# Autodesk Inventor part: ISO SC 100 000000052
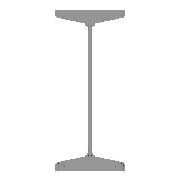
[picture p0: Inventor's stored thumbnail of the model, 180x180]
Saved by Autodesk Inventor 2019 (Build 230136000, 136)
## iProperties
_CCFamilyMember: 1
_CCFamilyDisplayName: ISO 657/16 - 1980 - Poutres en acier laminées à chaud - Partie 16: profilés en H (série métrique) - Cotes et propriétés de section
_FrameMemberDoc: Frame Member File
_Version: 15.0.0
_GetPNFromCC: 1
Created: 2018-07
Part Number: ISO SC 100 000000052
Material: Acier, doux
Description: Poutres en acier laminées à chaud - Partie 16: profilés en H (série métrique) - Cotes et propriétés de section
Document SubType Name: Modeling
Standard: ISO
Designer: Fabian Perrée
Standard Revision: First edition 1980-02-15
Standards Organization: ISO
Language: fr-FR
Size Designation: SC 100
Categories: <MemberInstance><Categories><Category DisplayName="Profilés" InternalName="089c4875-fa83-4c05-b084-43b9cc11f5ed" Mnemonic="GRDR"><CategoryParameter DisplayName=
Stock Number: SC 100
Density: 7.85 g/cm^3
Appearance: Semi-poli
Mass: 62799.5 g
Surface Area: 17060.8 cm^2
Volume: 7999.94 cm^3
IsCustomPart: 1
G_W: 100,000 mm
G_H: 100,000 mm
+B7F31D84-8E7F-44BF-867D-18DAA1A1DD99+DETAILDECOUPE1: Angle de coupe 67,38 deg
G_L: 3183,333 mm
+959F2517-F8C4-4F8C-BEA7-D48C5E0A7FF3+DETAILDECOUPE2: Angle de coupe 67,38 deg
Author: Fabian Perrée
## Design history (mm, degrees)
node "Plan de départ"
node "Plan de fin"
sketch "Esquisse"
  geometry: L1 (-3, 0)-(-3, -26.266); L2 (-13.33, -38.149)-(-44.835, -42.577); L3 (-50, -48.518)-(-50, -50); L4 (-50, -50)-(0, -50); L5 (-26.5, -50)-(-26.5, -40); L6 (-61.333, 0)-(81.777, 0); L7 (0, 0)-(0, -50); L8 (0, -60)-(0, 80); L9 (3, 0)-(3, -26.266); L10 (13.33, -38.149)-(44.835, -42.577); L11 (50, -48.518)-(50, -50); L12 (50, -50)-(0, -50); L13 (-3, 0)-(0, 0); L14 (-3, 0)-(-3, 26.266); L15 (-13.33, 38.149)-(-44.835, 42.577); L16 (-50, 48.518)-(-50, 50); L17 (-50, 50)-(0, 50); L18 (50, 48.518)-(50, 50); L19 (13.33, 38.149)-(44.835, 42.577); L20 (3, 0)-(3, 26.266); L21 (50, 50)-(0, 50); L22 (0, 108)-(0, -88) reference; L23 (-89.955, 0)-(110.399, 0) reference; A1 r 6 centre (-44, 48.518) between (-50, 48.518) and (-44.835, 42.577); A2 r 6 centre (44, 48.518) between (44.835, 42.577) and (50, 48.518); A3 r 6 centre (44, -48.518) between (50, -48.518) and (44.835, -42.577); A4 r 6 centre (-44, -48.518) between (-44.835, -42.577) and (-50, -48.518); A5 r 12 centre (-15, 26.266) between (-3, 26.266) and (-13.33, 38.149); A6 r 12 centre (15, 26.266) between (13.33, 38.149) and (3, 26.266); A7 r 12 centre (15, -26.266) between (3, -26.266) and (13.33, -38.149); A8 r 12 centre (-15, -26.266) between (-13.33, -38.149) and (-3, -26.266); 14 further points
  constraints: 42 end point, 24 point on line, 17 symmetric about line, 16 point on circle, 16 tangent, 8 centre point, 6 equal radius, 4 collinear, 2 perpendicular, 12 other
  dimensions: "d1" = 10 vertical distance of L3.end L5.end (= G_T1); "d2" = 23.5 distance between parallel lines of L5 L3 (= -0.25 x G_T + 0.25 x G_W); "d3" = 3 distance between parallel lines of L1 L7 (= 0.5 x G_T); "d4" = 50 distance between parallel lines of L7 L3 (= 0.5 x G_W); "d9" = 50 distance from line of L1.start L4 (= 0.5 x G_H); "d14" = 98 deg angle of L2 L1 (= G_NG); "d15" = 6 radius of A1 (= G_ER); "d16" = 12 radius of A5 (= G_IR)
extrude "Corps" new body sketch "Esquisse" stored distance "d5" = 3183.33333 (= G_L); taper "d6" = 0 deg
node "Driven Length"
  sketch "Sketch3"
    geometry: L1 (0, 0)-(10, 0) reference
    constraints: 2 end point, 1 horizontal
  workplane "Work Plane3"
  sketch "Sketch4"
    geometry: L1 (-2, 66.667)-(12, 66.667) reference; L2 (-2, 3250)-(12, 3250) reference
    dimensions: "d20" = 3183.33333 distance between parallel lines of L1 L2 (derived)
node "Plan de construction4"
feature "Scission1"
node "Plan de construction5"
feature "Scission2"
body "Solid1"
other parameters: "G_W" = 100 (= G_H) [user parameter; used in 2 equation terms], "G_H" = 100 [user parameter; used in 2 equation terms], "G_T" = 6 [user parameter; used in 2 equation terms], "G_T1" = 10 [user parameter; used in 1 equation term], "G_L" = 3183.33333 (= d20) [user parameter; used in 1 equation term], "G_ER" = 6 [user parameter; used in 1 equation term], "G_IR" = 12 [user parameter; used in 1 equation term], "G_NG" = 98 deg [user parameter; used in 1 equation term], "G_OFFSET_START" = -66.66667 [user parameter; used in 1 equation term], "G_OFFSET_END" = 0 [user parameter; used in 1 equation term], "d17" = 66.66667 (= -G_OFFSET_START), "d19" = 90 deg
